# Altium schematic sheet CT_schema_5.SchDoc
size 287 x 169 mm
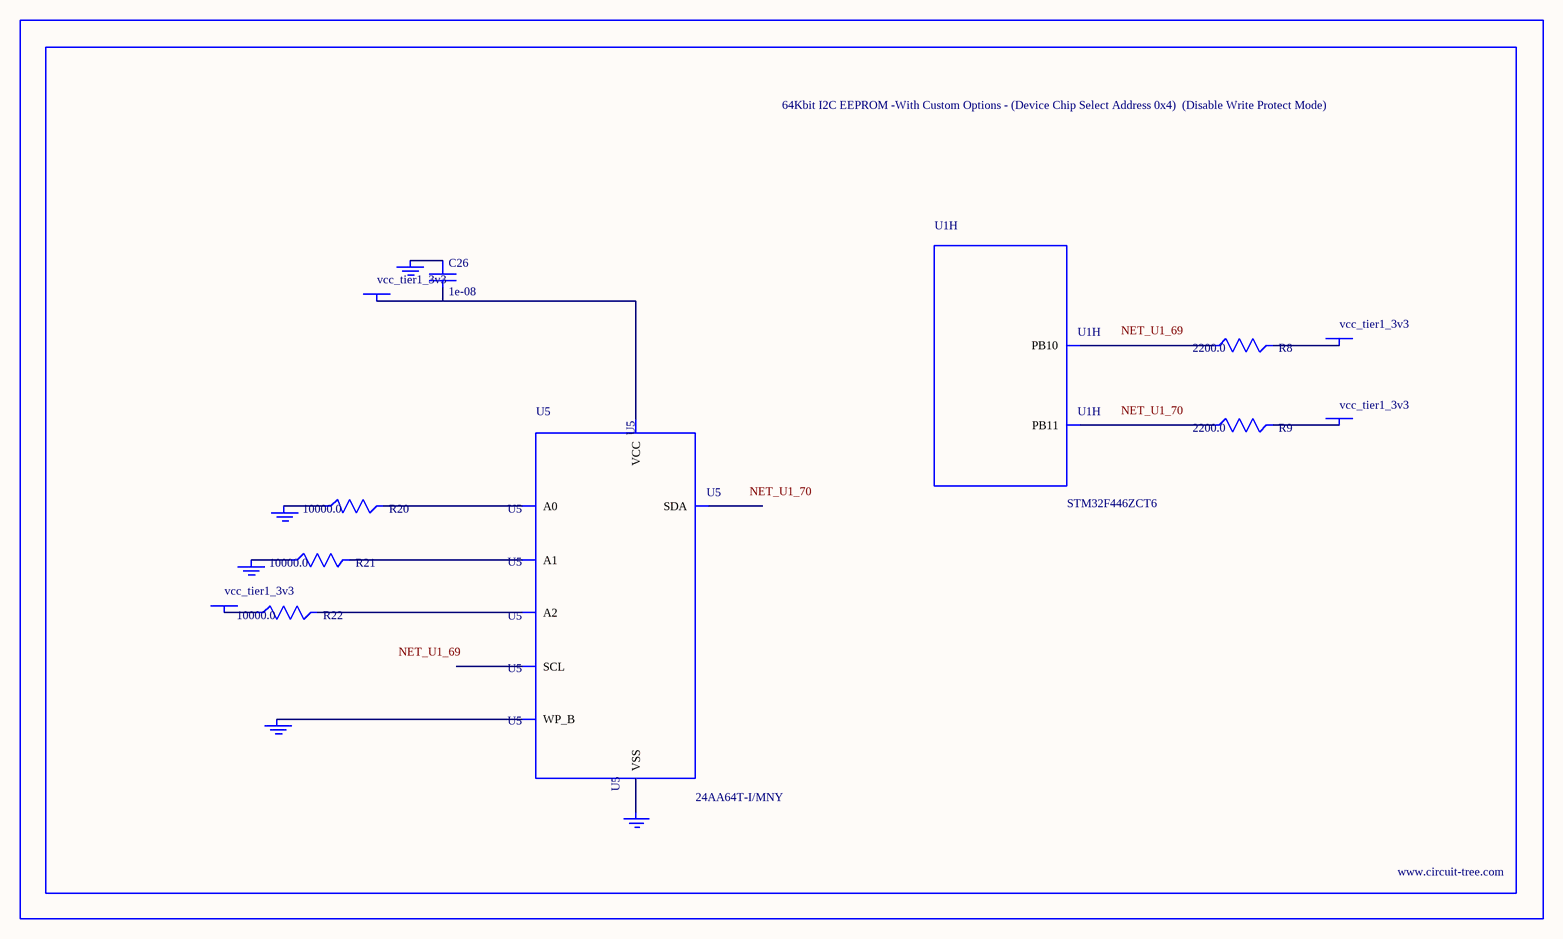
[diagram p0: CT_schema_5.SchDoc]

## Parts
BORDER4  (no value)
C26  1e-08  [C0402]
GND_INSTANCE_4_0  (no value)
GND_INSTANCE_4_1  (no value)
GND_INSTANCE_4_2  (no value)
GND_INSTANCE_4_3  (no value)
GND_INSTANCE_4_4  (no value)
POWER_INSTANCE_4_0  vcc_tier1_3v3
POWER_INSTANCE_4_1  vcc_tier1_3v3
POWER_INSTANCE_4_2  vcc_tier1_3v3
POWER_INSTANCE_4_3  vcc_tier1_3v3
R8  2200.0  [R0603]
R9  2200.0  [R0603]
R20  10000.0  [R0603]
R21  10000.0  [R0603]
R22  10000.0  [R0603]
U1  STM32F446ZCT6  [LQFP144]  (part H of 12)
U5  24AA64T-I/MNY  [TDFN-8/6MM]

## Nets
NetC26_1: C26.1 GND_INSTANCE_4_3.0(GND)
NetC26_2: C26.2 POWER_INSTANCE_4_1.0(PWR) U5.8(VCC)
NetGND_INSTANCE_4_0_0: GND_INSTANCE_4_0.0(GND) R20.1
NetGND_INSTANCE_4_1_0: GND_INSTANCE_4_1.0(GND) R21.1
NetGND_INSTANCE_4_2_0: GND_INSTANCE_4_2.0(GND) U5.7(WP_B)
NetGND_INSTANCE_4_4_0: GND_INSTANCE_4_4.0(GND) U5.4(VSS)
NetPOWER_INSTANCE_4_0_0: POWER_INSTANCE_4_0.0(PWR) R22.1
NetPOWER_INSTANCE_4_2_0: POWER_INSTANCE_4_2.0(PWR) R8.2
NetPOWER_INSTANCE_4_3_0: POWER_INSTANCE_4_3.0(PWR) R9.2
NetR8_1: R8.1 U1.69(PB10)
NetR9_1: R9.1 U1.70(PB11)
NetR20_2: R20.2 U5.1(A0)
NetR21_2: R21.2 U5.2(A1)
NetR22_2: R22.2 U5.3(A2)

Not connected (* = marked no-connect by the designer): U5 5(SDA) 6(SCL)

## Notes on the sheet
- Labels drawn without touching a wire or pin: NET_U1_69, NET_U1_70

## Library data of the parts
BORDER4 = BORDER_PAGE4
C26 = C0402C103K3RAC
GND_INSTANCE_4_0-GND_INSTANCE_4_4 = GND
POWER_INSTANCE_4_0-POWER_INSTANCE_4_3 = PWR
R8 R9 = RC0603JR-072K2L
R20-R22 = RC0603JR-0710KL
